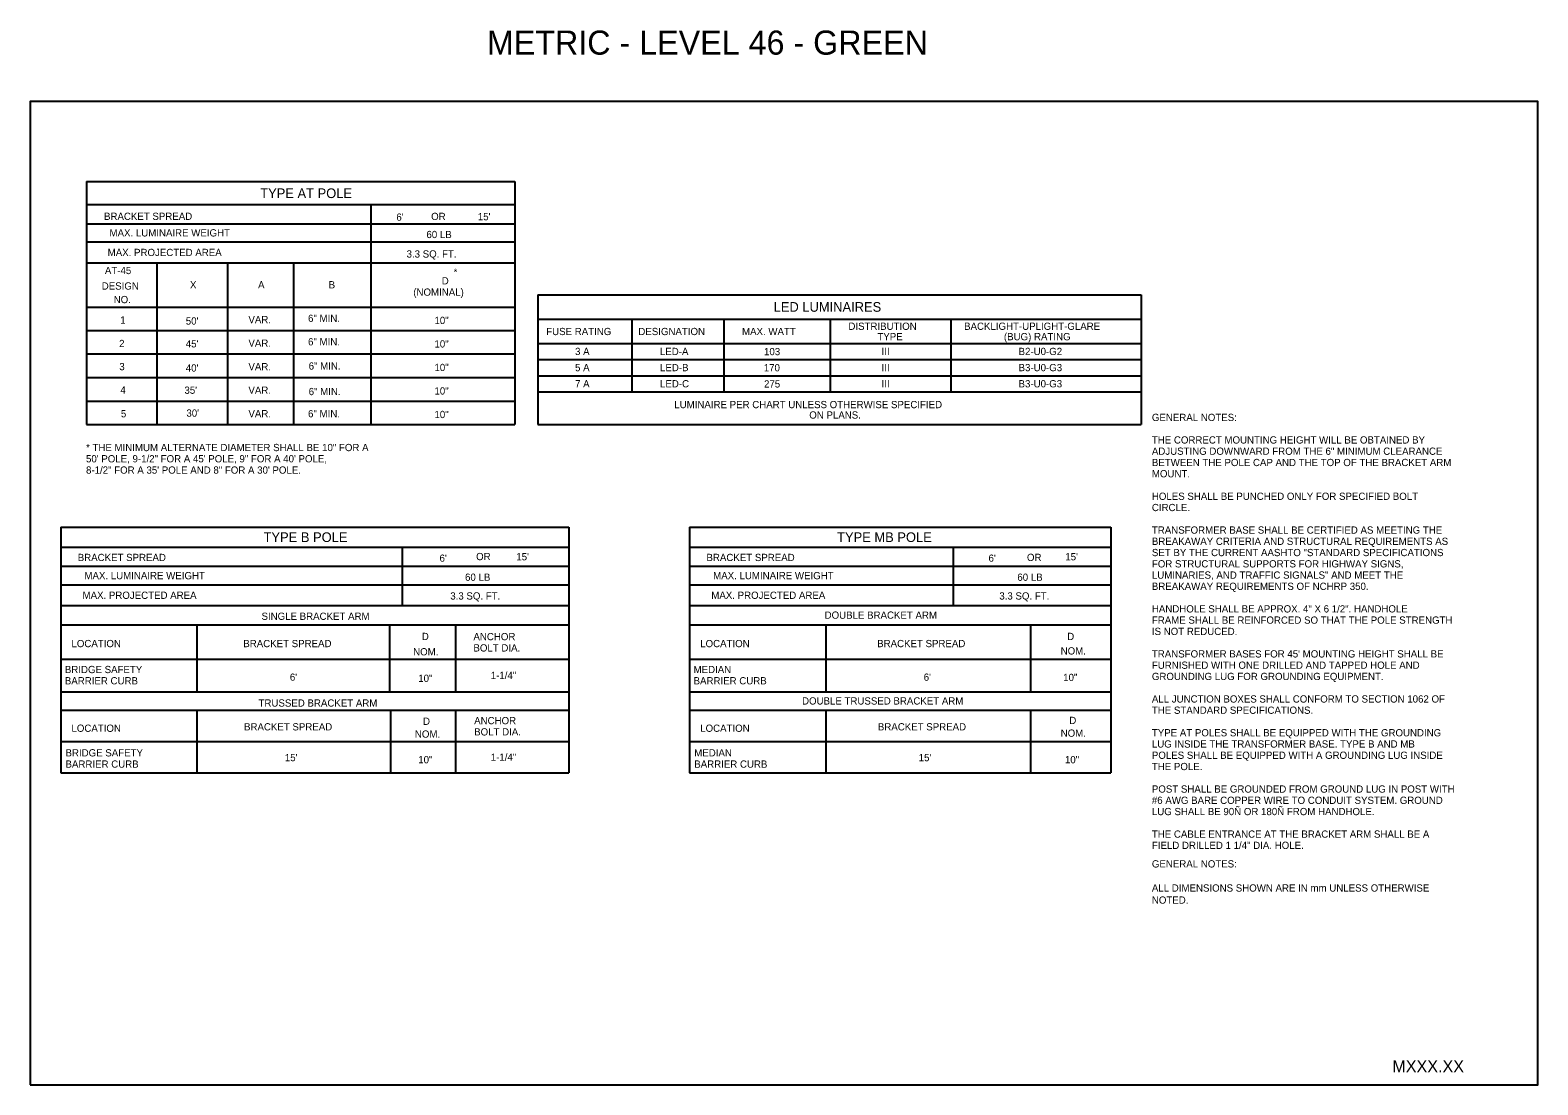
# Model space of a CAD drawing. Extents: x -439.1 to -407.9, y -458.1 to -436.2.
import ezdxf

# ---------------------------------------------------------------- set-up
doc = ezdxf.new("R2010")
doc.units = 0
for name, color, linetype in [('Draft_Named_Boundary', 7, 'Continuous'), ('Level 4', 7, 'Continuous'), ('Level 45', 7, 'Continuous'), ('Level 46', 7, 'Continuous')]:
    doc.layers.add(name, color=color, linetype=linetype)

msp = doc.modelspace()

# ---------------------------------------------------------------- linework, layer by layer
at = {"layer": 'Draft_Named_Boundary'}
msp.add_lwpolyline([(-439.109, -458.051), (-407.859, -458.051), (-407.859, -437.676), (-439.109, -437.676)], close=True, dxfattribs=at)
at = {"layer": 'Level 4'}
for p, q in [((-437.941, -439.333), (-437.941, -444.368)), ((-437.941, -439.333), (-429.063, -439.333)), ((-429.063, -439.333), (-429.063, -444.368)), ((-437.941, -439.81), (-429.063, -439.81)), ((-432.05, -439.81), (-432.05, -444.368)), ((-437.941, -440.209), (-429.063, -440.209)), ((-437.941, -440.586), (-429.063, -440.586)), ((-437.941, -441.015), (-429.063, -441.015)), ((-436.48, -441.013), (-436.48, -444.368)), ((-435.019, -441.013), (-435.019, -444.368)), ((-433.652, -441.013), (-433.652, -444.368)), ((-428.589, -441.681), (-416.082, -441.681)), ((-428.589, -441.681), (-428.589, -444.368)), ((-416.082, -441.681), (-416.082, -444.368)), ((-437.941, -441.934), (-429.063, -441.934)), ((-428.589, -442.183), (-416.082, -442.183)), ((-426.64, -442.183), (-426.64, -443.692)), ((-424.731, -442.183), (-424.731, -443.692)), ((-422.527, -442.183), (-422.527, -443.692)), ((-420.026, -442.183), (-420.026, -443.692)), ((-437.941, -442.42), (-429.063, -442.42)), ((-428.589, -442.687), (-416.082, -442.687)), ((-437.941, -442.907), (-429.063, -442.907)), ((-428.589, -443.022), (-416.082, -443.022)), ((-428.589, -443.022), (-416.082, -443.022)), ((-437.941, -443.395), (-429.063, -443.395)), ((-428.589, -443.357), (-416.082, -443.357)), ((-428.589, -443.357), (-416.082, -443.357)), ((-428.589, -443.692), (-416.082, -443.692)), ((-437.941, -443.882), (-429.063, -443.882)), ((-437.941, -444.368), (-429.063, -444.368)), ((-428.589, -444.368), (-416.082, -444.368)), ((-438.473, -446.496), (-427.943, -446.496)), ((-438.473, -446.496), (-438.473, -451.584)), ((-427.943, -446.496), (-427.943, -451.584)), ((-425.441, -446.496), (-425.441, -451.584)), ((-425.441, -446.496), (-416.708, -446.496)), ((-416.708, -446.496), (-416.708, -451.584)), ((-438.473, -446.909), (-427.943, -446.909)), ((-431.392, -448.118), (-431.392, -446.909)), ((-425.441, -446.909), (-416.708, -446.909)), ((-419.973, -448.105), (-419.973, -446.896)), ((-438.473, -447.304), (-427.943, -447.304)), ((-425.441, -447.304), (-416.708, -447.304)), ((-438.473, -447.689), (-427.943, -447.689)), ((-425.441, -447.689), (-416.708, -447.689)), ((-438.473, -448.118), (-427.943, -448.118)), ((-425.441, -448.118), (-416.708, -448.118)), ((-438.473, -448.517), (-427.943, -448.517)), ((-431.66, -448.517), (-431.66, -449.905)), ((-430.291, -448.517), (-430.291, -449.905)), ((-425.441, -448.517), (-416.708, -448.517)), ((-418.373, -448.517), (-418.373, -449.905)), ((-438.473, -449.228), (-427.943, -449.228)), ((-425.441, -449.228), (-416.708, -449.228)), ((-438.473, -449.905), (-427.943, -449.905)), ((-425.441, -449.905), (-416.708, -449.905)), ((-438.473, -450.258), (-438.473, -450.287)), ((-438.473, -450.287), (-427.943, -450.287)), ((-435.652, -450.287), (-435.652, -451.584)), ((-431.639, -450.287), (-431.639, -451.584)), ((-430.291, -450.287), (-430.291, -451.584)), ((-425.441, -450.258), (-425.441, -450.287)), ((-425.441, -450.287), (-425.441, -450.403)), ((-425.441, -450.287), (-416.708, -450.287)), ((-422.62, -450.287), (-422.62, -451.584)), ((-418.373, -450.287), (-418.373, -451.584)), ((-438.473, -450.939), (-427.943, -450.939)), ((-425.441, -450.939), (-416.708, -450.939)), ((-438.473, -451.584), (-427.943, -451.584)), ((-425.441, -451.584), (-416.708, -451.584))]:
    msp.add_line(p, q, dxfattribs=at)
for points in [[(-435.652, -448.517), (-435.652, -449.905)], [(-422.62, -448.517), (-422.62, -449.905)]]:
    msp.add_lwpolyline(points, dxfattribs=at)

# ---------------------------------------------------------------- texts
for s, height, p in [('TYPE AT POLE', 0.2, (-434.34, -439.676)), ('BRACKET SPREAD', 0.15, (-437.578, -440.129)), ('OR', 0.15, (-430.798, -440.131)), ('MAX. LUMINAIRE WEIGHT', 0.15, (-437.464, -440.472)), ('MAX. PROJECTED AREA', 0.15, (-437.502, -440.878)), ('DESIGN', 0.15, (-437.625, -441.573)), ('NO.', 0.15, (-437.377, -441.854)), ('LED LUMINAIRES', 0.2, (-423.698, -442.032)), ('1', 0.15, (-437.242, -442.278)), ('VAR.', 0.15, (-434.585, -442.27)), ('FUSE RATING', 0.15, (-428.412, -442.516)), ('DESIGNATION', 0.15, (-426.503, -442.516)), ('MAX. WATT', 0.15, (-424.354, -442.516)), ('DISTRIBUTION', 0.15, (-422.149, -442.407)), ('TYPE', 0.15, (-421.548, -442.623)), ('BACKLIGHT-UPLIGHT-GLARE', 0.15, (-419.751, -442.407)), ('(BUG) RATING', 0.15, (-418.926, -442.623)), ('2', 0.15, (-437.265, -442.765)), ('VAR.', 0.15, (-434.585, -442.757)), ('3 A', 0.15, (-427.815, -442.929)), ('LED-A', 0.15, (-426.056, -442.929)), ('103', 0.15, (-423.898, -442.932)), ('III', 0.15, (-421.461, -442.929)), ('B2-U0-G2', 0.15, (-418.622, -442.929)), ('3', 0.15, (-437.261, -443.243)), ('VAR.', 0.15, (-434.585, -443.245)), ('5 A', 0.15, (-427.815, -443.264)), ('LED-B', 0.15, (-426.054, -443.264)), ('170', 0.15, (-423.903, -443.267)), ('III', 0.15, (-421.461, -443.264)), ('B3-U0-G3', 0.15, (-418.622, -443.264)), ('4', 0.15, (-437.239, -443.728)), ('VAR.', 0.15, (-434.585, -443.732)), ('7 A', 0.15, (-427.815, -443.599)), ('LED-C', 0.15, (-426.054, -443.599)), ('275', 0.15, (-423.898, -443.602)), ('III', 0.15, (-421.461, -443.599)), ('B3-U0-G3', 0.15, (-418.622, -443.599)), ('LUMINAIRE PER CHART UNLESS OTHERWISE SPECIFIED', 0.15, (-425.758, -444.03)), ('5', 0.15, (-437.228, -444.219)), ('VAR.', 0.15, (-434.585, -444.219)), ('ON PLANS.', 0.15, (-422.96, -444.246)), ('TYPE B POLE', 0.2, (-434.271, -446.803)), ('TYPE MB POLE', 0.2, (-422.383, -446.803)), ('BRACKET SPREAD', 0.15, (-438.123, -447.198)), ('OR', 0.15, (-429.866, -447.179)), ('BRACKET SPREAD', 0.15, (-425.091, -447.198)), ('OR', 0.15, (-418.448, -447.196)), ('MAX. LUMINAIRE WEIGHT', 0.15, (-437.984, -447.575)), ('MAX. LUMINAIRE WEIGHT', 0.15, (-424.952, -447.575)), ('MAX. PROJECTED AREA', 0.15, (-438.023, -447.981)), ('MAX. PROJECTED AREA', 0.15, (-424.991, -447.981)), ('SINGLE BRACKET ARM', 0.15, (-434.314, -448.416)), ('DOUBLE BRACKET ARM', 0.15, (-422.642, -448.393)), ('D', 0.15, (-430.991, -448.834)), ('ANCHOR', 0.15, (-429.921, -448.838)), ('D', 0.15, (-417.614, -448.834)), ('LOCATION', 0.15, (-438.253, -448.982)), ('BRACKET SPREAD', 0.15, (-434.691, -448.982)), ('NOM.', 0.15, (-431.171, -449.152)), ('BOLT DIA.', 0.15, (-429.921, -449.072)), ('LOCATION', 0.15, (-425.221, -448.982)), ('BRACKET SPREAD', 0.15, (-421.553, -448.982)), ('NOM.', 0.15, (-417.749, -449.134)), ('BRIDGE SAFETY', 0.15, (-438.39, -449.52)), ('MEDIAN', 0.15, (-425.358, -449.52)), ('BARRIER CURB', 0.15, (-438.39, -449.753)), ('BARRIER CURB', 0.15, (-425.358, -449.753)), ('TRUSSED BRACKET ARM', 0.15, (-434.375, -450.214)), ('DOUBLE TRUSSED BRACKET ARM', 0.15, (-423.11, -450.171)), ('LOCATION', 0.15, (-438.253, -450.736)), ('BRACKET SPREAD', 0.15, (-434.676, -450.707)), ('D', 0.15, (-430.966, -450.592)), ('ANCHOR', 0.15, (-429.906, -450.579)), ('LOCATION', 0.15, (-425.221, -450.736)), ('BRACKET SPREAD', 0.15, (-421.538, -450.707)), ('D', 0.15, (-417.57, -450.574)), ('NOM.', 0.15, (-431.135, -450.857)), ('BOLT DIA.', 0.15, (-429.906, -450.812)), ('NOM.', 0.15, (-417.749, -450.838)), ('BRIDGE SAFETY', 0.15, (-438.376, -451.246)), ('MEDIAN', 0.15, (-425.344, -451.246)), ('BARRIER CURB', 0.15, (-438.376, -451.479)), ('BARRIER CURB', 0.15, (-425.344, -451.479))]:
    msp.add_text(s, height=height, dxfattribs=at).set_placement(p)
at = {"layer": 'Level 45'}
for s, p in [("6'", (-431.518, -440.146)), ("15'", (-429.83, -440.136)), ('60 LB', (-430.895, -440.506)), ('3.3 SQ. FT.', (-431.307, -440.909)), ('AT-45', (-437.56, -441.252)), ('*', (-430.332, -441.285)), ('X', (-435.796, -441.548)), ('A', (-434.385, -441.548)), ('B', (-432.922, -441.548)), ('(NOMINAL)', (-431.168, -441.7)), ('D', (-430.578, -441.466)), ("50'", (-435.883, -442.298)), ('6" MIN.', (-433.349, -442.243)), ('10"', (-430.729, -442.286)), ("45'", (-435.883, -442.771)), ('6" MIN.', (-433.349, -442.729)), ('10"', (-430.729, -442.773)), ("40'", (-435.883, -443.272)), ('6" MIN.', (-433.336, -443.231)), ('10"', (-430.729, -443.261)), ("35'", (-435.911, -443.732)), ('6" MIN.', (-433.336, -443.76)), ('10"', (-430.729, -443.748)), ("30'", (-435.87, -444.206)), ('6" MIN.', (-433.349, -444.219)), ('10"', (-430.729, -444.235)), ('GENERAL NOTES:', (-415.859, -444.296)), ('THE CORRECT MOUNTING HEIGHT WILL BE OBTAINED BY', (-415.859, -444.763)), ('* THE MINIMUM ALTERNATE DIAMETER SHALL BE 10" FOR A', (-437.951, -444.92)), ('50\' POLE, 9-1/2" FOR A 45\' POLE, 9" FOR A 40\' POLE,', (-437.951, -445.153)), ('ADJUSTING DOWNWARD FROM THE 6" MINIMUM CLEARANCE', (-415.859, -444.996)), ('8-1/2" FOR A 35\' POLE AND 8" FOR A 30\' POLE.', (-437.951, -445.387)), ('BETWEEN THE POLE CAP AND THE TOP OF THE BRACKET ARM', (-415.859, -445.23)), ('MOUNT.', (-415.859, -445.463)), ('HOLES SHALL BE PUNCHED ONLY FOR SPECIFIED BOLT ', (-415.859, -445.93)), ('CIRCLE.', (-415.859, -446.163)), ('TRANSFORMER BASE SHALL BE CERTIFIED AS MEETING THE ', (-415.859, -446.63)), ('BREAKAWAY CRITERIA AND STRUCTURAL REQUIREMENTS AS ', (-415.859, -446.863)), ("6'", (-430.624, -447.212)), ("15'", (-429.033, -447.183)), ("6'", (-419.245, -447.212)), ("15'", (-417.654, -447.183)), ('SET BY THE CURRENT AASHTO "STANDARD SPECIFICATIONS ', (-415.859, -447.096)), ('FOR STRUCTURAL SUPPORTS FOR HIGHWAY SIGNS, ', (-415.859, -447.33)), ('60 LB', (-430.095, -447.607)), ('60 LB', (-418.647, -447.607)), ('LUMINARIES, AND TRAFFIC SIGNALS" AND MEET THE ', (-415.859, -447.563)), ('BREAKAWAY REQUIREMENTS OF NCHRP 350.', (-415.859, -447.796)), ('3.3 SQ. FT.', (-430.401, -447.995)), ('3.3 SQ. FT.', (-419.021, -447.995)), ('HANDHOLE SHALL BE APPROX. 4" X 6 1/2". HANDHOLE', (-415.859, -448.263)), ('FRAME SHALL BE REINFORCED SO THAT THE POLE STRENGTH ', (-415.859, -448.496)), ('IS NOT REDUCED.', (-415.859, -448.73)), ("TRANSFORMER BASES FOR 45' MOUNTING HEIGHT SHALL BE", (-415.859, -449.196)), ('FURNISHED WITH ONE DRILLED AND TAPPED HOLE AND ', (-415.859, -449.43)), ("6'", (-433.726, -449.678)), ('10"', (-431.065, -449.702)), ('1-1/4"', (-429.562, -449.642)), ("6'", (-420.588, -449.678)), ('10"', (-417.697, -449.684)), ('GROUNDING LUG FOR GROUNDING EQUIPMENT.', (-415.859, -449.663)), ('ALL JUNCTION BOXES SHALL CONFORM TO SECTION 1062 OF ', (-415.859, -450.13)), ('THE STANDARD SPECIFICATIONS.', (-415.859, -450.363)), ('TYPE AT POLES SHALL BE EQUIPPED WITH THE GROUNDING ', (-415.859, -450.83)), ('LUG INSIDE THE TRANSFORMER BASE. TYPE B AND MB ', (-415.859, -451.063)), ("15'", (-433.83, -451.345)), ('10"', (-431.065, -451.388)), ('1-1/4"', (-429.562, -451.336)), ("15'", (-420.692, -451.345)), ('10"', (-417.661, -451.388)), ('POLES SHALL BE EQUIPPED WITH A GROUNDING LUG INSIDE ', (-415.859, -451.296)), ('THE POLE.', (-415.859, -451.53)), ('POST SHALL BE GROUNDED FROM GROUND LUG IN POST WITH ', (-415.859, -451.996)), ('#6 AWG BARE COPPER WIRE TO CONDUIT SYSTEM. GROUND ', (-415.859, -452.23)), ('LUG SHALL BE 90Ñ OR 180Ñ FROM HANDHOLE.', (-415.859, -452.463)), ('THE CABLE ENTRANCE AT THE BRACKET ARM SHALL BE A ', (-415.859, -452.93)), ('FIELD DRILLED 1 1/4" DIA. HOLE.', (-415.859, -453.163))]:
    msp.add_text(s, height=0.15, dxfattribs=at).set_placement(p)
at = {"layer": 'Level 46'}
for s, height, p in [('METRIC - LEVEL 46 - GREEN', 0.5, (-429.642, -436.705)), ('GENERAL NOTES:', 0.15, (-415.859, -453.547)), ('ALL DIMENSIONS SHOWN ARE IN mm UNLESS OTHERWISE ', 0.15, (-415.859, -454.047)), ('NOTED.', 0.15, (-415.859, -454.297)), ('MXXX.XX', 0.25, (-410.875, -457.792))]:
    msp.add_text(s, height=height, dxfattribs=at).set_placement(p)

doc.saveas('drawing.dxf')
